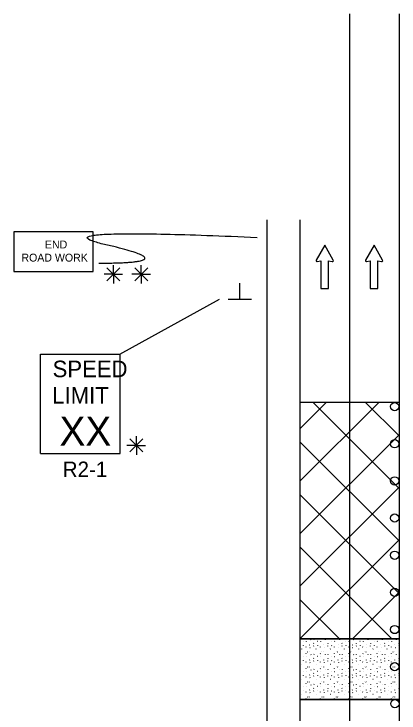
# Model space of a CAD drawing. Extents: x 16489 to 18480, y 5759 to 7026.
# Drawn here: x 16749.1 to 16935.7, y 6687.7 to 7026.4 of the extents above; entities that cross this region are included whole.
import ezdxf

# ---------------------------------------------------------------- set-up
doc = ezdxf.new("R2010")
doc.units = 0
for name, color, linetype in [('ALI_LEGAL_EX', 7, 'Continuous'), ('MT_SCRATCH_LEVEL_A', 7, 'Continuous'), ('MT_SCRATCH_LEVEL_E', 7, 'Continuous'), ('PAVT_EDGE_EX', 7, 'Continuous'), ('TRAFFIC_SIGNS_PR', 7, 'Continuous'), ('TYPICAL_TEXT_DIMEN_PR', 7, 'Continuous')]:
    doc.layers.add(name, color=color, linetype=linetype)

msp = doc.modelspace()

# ---------------------------------------------------------------- linework, layer by layer
at = {"layer": 'ALI_LEGAL_EX'}
for p, q in [((16911.66, 7026.35), (16911.66, 6197.16)), ((16935.66, 7026.35), (16935.66, 6197.16)), ((16935.66, 7026.35), (16935.66, 6197.16))]:
    msp.add_line(p, q, dxfattribs=at)
for points in [[(16911.66, 6926.35), (16911.66, 6901.35)], [(16935.66, 6926.35), (16935.66, 6901.35)], [(16911.66, 6826.35), (16911.66, 6801.35)], [(16935.66, 6826.35), (16935.66, 6801.35)], [(16911.66, 6726.35), (16911.66, 6701.35)], [(16935.66, 6726.35), (16935.66, 6701.35)]]:
    msp.add_lwpolyline(points, dxfattribs=at)
at = {"layer": 'MT_SCRATCH_LEVEL_A'}
for p, q in [((16935.66, 6838.16), (16887.66, 6838.16)), ((16935.66, 6723.62), (16887.66, 6723.62)), ((16935.66, 6694.2), (16887.66, 6694.2))]:
    msp.add_line(p, q, dxfattribs=at)
at = {"layer": 'MT_SCRATCH_LEVEL_E'}
for p, q in [((16899.66, 6914.3), (16895.55, 6907.06)), ((16903.81, 6907.06), (16899.66, 6914.3)), ((16923.57, 6914.3), (16919.46, 6907.06)), ((16927.71, 6907.06), (16923.57, 6914.3)), ((16896.03, 6906.37), (16897.81, 6906.69)), ((16897.81, 6906.69), (16897.81, 6893.43)), ((16901.55, 6893.43), (16901.55, 6906.69)), ((16901.55, 6906.69), (16903.33, 6906.37)), ((16919.94, 6906.37), (16921.72, 6906.69)), ((16921.72, 6906.69), (16921.72, 6893.43)), ((16925.46, 6893.43), (16925.46, 6906.69)), ((16925.46, 6906.69), (16927.23, 6906.37)), ((16897.81, 6893.43), (16901.55, 6893.43)), ((16921.72, 6893.43), (16925.46, 6893.43))]:
    msp.add_line(p, q, dxfattribs=at)
for centre, start, end in [((16895.96, 6906.83), 150.4248, 279.9638), ((16903.4, 6906.83), 260.0362, 29.7731), ((16919.86, 6906.83), 150.4248, 279.9638), ((16927.3, 6906.83), 260.0362, 29.7731)]:
    msp.add_arc(centre, 0.463, start, end, dxfattribs=at)
at = {"layer": 'PAVT_EDGE_EX'}
for p, q in [((16871.66, 6926.66), (16871.66, 6108.7)), ((16887.66, 6926.66), (16887.66, 6108.7)), ((16935.66, 6838.16), (16887.66, 6838.16)), ((16887.66, 6838.16), (16887.66, 6723.62)), ((16887.66, 6825.45), (16900.38, 6838.16)), ((16887.66, 6799.99), (16925.83, 6838.16)), ((16935.66, 6796.54), (16894.04, 6838.16)), ((16935.66, 6822), (16919.5, 6838.16)), ((16887.66, 6774.54), (16935.66, 6822.54)), ((16935.66, 6771.08), (16887.66, 6819.08)), ((16887.66, 6749.08), (16935.66, 6797.08)), ((16935.66, 6745.63), (16887.66, 6793.63)), ((16887.66, 6723.62), (16935.66, 6771.62)), ((16932.21, 6723.62), (16887.66, 6768.17)), ((16913.12, 6723.62), (16935.66, 6746.17)), ((16906.76, 6723.62), (16887.66, 6742.72)), ((16887.66, 6723.62), (16935.66, 6723.62)), ((16935.66, 6723.62), (16887.66, 6723.62)), ((16887.66, 6723.62), (16887.66, 6694.2)), ((16887.66, 6723.62), (16887.66, 6723.62)), ((16889.16, 6722.57), (16889.21, 6722.5)), ((16890.69, 6722.44), (16890.74, 6722.36)), ((16892.98, 6723.25), (16893.03, 6723.18)), ((16894.43, 6723.4), (16894.48, 6723.52)), ((16896.05, 6722.57), (16896.1, 6722.5)), ((16897.58, 6722.44), (16897.63, 6722.36)), ((16899.87, 6723.25), (16899.92, 6723.18)), ((16901.32, 6723.4), (16901.37, 6723.52)), ((16902.94, 6722.57), (16902.99, 6722.5)), ((16904.47, 6722.44), (16904.52, 6722.36)), ((16906.76, 6723.25), (16906.81, 6723.18)), ((16908.21, 6723.4), (16908.26, 6723.52)), ((16909.82, 6722.57), (16909.88, 6722.5)), ((16911.35, 6722.44), (16911.4, 6722.36)), ((16913.64, 6723.25), (16913.69, 6723.18)), ((16915.09, 6723.4), (16915.14, 6723.52)), ((16916.71, 6722.57), (16916.76, 6722.5)), ((16918.24, 6722.44), (16918.29, 6722.36)), ((16920.53, 6723.25), (16920.58, 6723.18)), ((16921.98, 6723.4), (16922.03, 6723.52)), ((16923.6, 6722.57), (16923.65, 6722.5)), ((16925.13, 6722.44), (16925.18, 6722.36)), ((16927.42, 6723.25), (16927.47, 6723.18)), ((16928.87, 6723.4), (16928.92, 6723.52)), ((16930.49, 6722.57), (16930.54, 6722.5)), ((16932.02, 6722.44), (16932.07, 6722.36)), ((16934.31, 6723.25), (16934.36, 6723.18)), ((16889.21, 6720.37), (16889.26, 6720.29)), ((16890.49, 6719.79), (16890.5, 6719.67)), ((16892.33, 6720.65), (16892.38, 6720.76)), ((16892.52, 6719.45), (16892.57, 6719.37)), ((16894.26, 6721.52), (16894.31, 6721.44)), ((16894.3, 6720.11), (16894.35, 6720.23)), ((16896.1, 6720.37), (16896.15, 6720.29)), ((16897.38, 6719.79), (16897.39, 6719.67)), ((16899.22, 6720.65), (16899.27, 6720.76)), ((16899.41, 6719.45), (16899.46, 6719.37)), ((16901.15, 6721.52), (16901.2, 6721.44)), ((16901.19, 6720.11), (16901.24, 6720.23)), ((16902.99, 6720.37), (16903.04, 6720.29)), ((16904.27, 6719.79), (16904.28, 6719.67)), ((16906.11, 6720.65), (16906.16, 6720.76)), ((16906.3, 6719.45), (16906.35, 6719.37)), ((16908.03, 6721.52), (16908.08, 6721.44)), ((16908.08, 6720.11), (16908.13, 6720.23)), ((16909.87, 6720.37), (16909.92, 6720.29)), ((16911.15, 6719.79), (16911.17, 6719.67)), ((16912.99, 6720.65), (16913.05, 6720.76)), ((16913.18, 6719.45), (16913.24, 6719.37)), ((16914.92, 6721.52), (16914.97, 6721.44)), ((16914.96, 6720.11), (16915.01, 6720.23)), ((16916.76, 6720.37), (16916.81, 6720.29)), ((16918.04, 6719.79), (16918.05, 6719.67)), ((16919.88, 6720.65), (16919.93, 6720.76)), ((16920.07, 6719.45), (16920.12, 6719.37)), ((16921.81, 6721.52), (16921.86, 6721.44)), ((16921.85, 6720.11), (16921.9, 6720.23)), ((16923.65, 6720.37), (16923.7, 6720.29)), ((16924.93, 6719.79), (16924.94, 6719.67)), ((16926.77, 6720.65), (16926.82, 6720.76)), ((16926.96, 6719.45), (16927.01, 6719.37)), ((16928.7, 6721.52), (16928.75, 6721.44)), ((16928.74, 6720.11), (16928.79, 6720.23)), ((16930.53, 6720.37), (16930.59, 6720.29)), ((16931.82, 6719.79), (16931.83, 6719.67)), ((16933.66, 6720.65), (16933.71, 6720.76)), ((16933.85, 6719.45), (16933.9, 6719.37)), ((16935.58, 6721.52), (16935.64, 6721.44)), ((16935.63, 6720.11), (16935.66, 6720.2)), ((16888.59, 6718.61), (16888.64, 6718.73)), ((16890.61, 6716.42), (16890.66, 6716.53)), ((16891.38, 6717.38), (16891.43, 6717.3)), ((16892.11, 6717.35), (16892.16, 6717.27)), ((16892.98, 6715.97), (16893.03, 6715.89)), ((16894.43, 6716.12), (16894.48, 6716.24)), ((16895.48, 6718.61), (16895.53, 6718.73)), ((16897.5, 6716.42), (16897.55, 6716.53)), ((16898.26, 6717.38), (16898.31, 6717.3)), ((16899, 6717.35), (16899.05, 6717.27)), ((16899.87, 6715.97), (16899.92, 6715.89)), ((16901.32, 6716.12), (16901.37, 6716.24)), ((16902.37, 6718.61), (16902.42, 6718.73)), ((16904.39, 6716.42), (16904.44, 6716.53)), ((16905.15, 6717.38), (16905.2, 6717.3)), ((16905.89, 6717.35), (16905.94, 6717.27)), ((16906.76, 6715.97), (16906.81, 6715.89)), ((16908.21, 6716.12), (16908.26, 6716.24)), ((16909.25, 6718.61), (16909.31, 6718.73)), ((16911.27, 6716.42), (16911.33, 6716.53)), ((16912.04, 6717.38), (16912.09, 6717.3)), ((16912.78, 6717.35), (16912.83, 6717.27)), ((16913.64, 6715.97), (16913.69, 6715.89)), ((16915.09, 6716.12), (16915.14, 6716.24)), ((16916.14, 6718.61), (16916.19, 6718.73)), ((16918.16, 6716.42), (16918.21, 6716.53)), ((16918.92, 6717.38), (16918.98, 6717.3)), ((16919.66, 6717.35), (16919.71, 6717.27)), ((16920.53, 6715.97), (16920.58, 6715.89)), ((16921.98, 6716.12), (16922.03, 6716.24)), ((16923.03, 6718.61), (16923.08, 6718.73)), ((16925.05, 6716.42), (16925.1, 6716.53)), ((16925.81, 6717.38), (16925.86, 6717.3)), ((16926.55, 6717.35), (16926.6, 6717.27)), ((16927.42, 6715.97), (16927.47, 6715.89)), ((16928.87, 6716.12), (16928.92, 6716.24)), ((16929.92, 6718.61), (16929.97, 6718.73)), ((16931.94, 6716.42), (16931.99, 6716.53)), ((16932.7, 6717.38), (16932.75, 6717.3)), ((16933.44, 6717.35), (16933.49, 6717.27)), ((16934.31, 6715.97), (16934.36, 6715.89)), ((16889.16, 6715.29), (16889.21, 6715.21)), ((16889.21, 6713.08), (16889.26, 6713)), ((16890.49, 6712.51), (16890.5, 6712.39)), ((16890.69, 6715.15), (16890.74, 6715.07)), ((16892.33, 6713.36), (16892.38, 6713.48)), ((16892.52, 6712.16), (16892.57, 6712.08)), ((16894.26, 6714.23), (16894.31, 6714.15)), ((16894.3, 6712.83), (16894.35, 6712.95)), ((16896.05, 6715.29), (16896.1, 6715.21)), ((16896.1, 6713.08), (16896.15, 6713)), ((16897.38, 6712.51), (16897.39, 6712.39)), ((16897.58, 6715.15), (16897.63, 6715.07)), ((16899.22, 6713.36), (16899.27, 6713.48)), ((16899.41, 6712.16), (16899.46, 6712.08)), ((16901.15, 6714.23), (16901.2, 6714.15)), ((16901.19, 6712.83), (16901.24, 6712.95)), ((16902.94, 6715.29), (16902.99, 6715.21)), ((16902.99, 6713.08), (16903.04, 6713)), ((16904.27, 6712.51), (16904.28, 6712.39)), ((16904.47, 6715.15), (16904.52, 6715.07)), ((16906.11, 6713.36), (16906.16, 6713.48)), ((16906.3, 6712.16), (16906.35, 6712.08)), ((16908.03, 6714.23), (16908.08, 6714.15)), ((16908.08, 6712.83), (16908.13, 6712.95)), ((16909.82, 6715.29), (16909.88, 6715.21)), ((16909.87, 6713.08), (16909.92, 6713)), ((16911.15, 6712.51), (16911.17, 6712.39)), ((16911.35, 6715.15), (16911.4, 6715.07)), ((16912.99, 6713.36), (16913.05, 6713.48)), ((16913.18, 6712.16), (16913.24, 6712.08)), ((16914.92, 6714.23), (16914.97, 6714.15)), ((16914.96, 6712.83), (16915.01, 6712.95)), ((16916.71, 6715.29), (16916.76, 6715.21)), ((16916.76, 6713.08), (16916.81, 6713)), ((16918.04, 6712.51), (16918.05, 6712.39)), ((16918.24, 6715.15), (16918.29, 6715.07)), ((16919.88, 6713.36), (16919.93, 6713.48)), ((16920.07, 6712.16), (16920.12, 6712.08)), ((16921.81, 6714.23), (16921.86, 6714.15)), ((16921.85, 6712.83), (16921.9, 6712.95)), ((16923.6, 6715.29), (16923.65, 6715.21)), ((16923.65, 6713.08), (16923.7, 6713)), ((16924.93, 6712.51), (16924.94, 6712.39)), ((16925.13, 6715.15), (16925.18, 6715.07)), ((16926.77, 6713.36), (16926.82, 6713.48)), ((16926.96, 6712.16), (16927.01, 6712.08)), ((16928.7, 6714.23), (16928.75, 6714.15)), ((16928.74, 6712.83), (16928.79, 6712.95)), ((16930.49, 6715.29), (16930.54, 6715.21)), ((16930.53, 6713.08), (16930.59, 6713)), ((16931.82, 6712.51), (16931.83, 6712.39)), ((16932.02, 6715.15), (16932.07, 6715.07)), ((16933.66, 6713.36), (16933.71, 6713.48)), ((16933.85, 6712.16), (16933.9, 6712.08)), ((16935.58, 6714.23), (16935.64, 6714.15)), ((16935.63, 6712.83), (16935.66, 6712.92)), ((16888.59, 6711.33), (16888.64, 6711.44)), ((16890.61, 6709.13), (16890.66, 6709.25)), ((16891.38, 6710.09), (16891.43, 6710.01)), ((16892.11, 6710.06), (16892.16, 6709.98)), ((16894.43, 6708.83), (16894.48, 6708.95)), ((16895.48, 6711.33), (16895.53, 6711.44)), ((16897.5, 6709.13), (16897.55, 6709.25)), ((16898.26, 6710.09), (16898.31, 6710.01)), ((16899, 6710.06), (16899.05, 6709.98)), ((16901.32, 6708.83), (16901.37, 6708.95)), ((16902.37, 6711.33), (16902.42, 6711.44)), ((16904.39, 6709.13), (16904.44, 6709.25)), ((16905.15, 6710.09), (16905.2, 6710.01)), ((16905.89, 6710.06), (16905.94, 6709.98)), ((16908.21, 6708.83), (16908.26, 6708.95)), ((16909.25, 6711.33), (16909.31, 6711.44)), ((16911.27, 6709.13), (16911.33, 6709.25)), ((16912.04, 6710.09), (16912.09, 6710.01)), ((16912.78, 6710.06), (16912.83, 6709.98)), ((16915.09, 6708.83), (16915.14, 6708.95)), ((16916.14, 6711.33), (16916.19, 6711.44)), ((16918.16, 6709.13), (16918.21, 6709.25)), ((16918.92, 6710.09), (16918.98, 6710.01)), ((16919.66, 6710.06), (16919.71, 6709.98)), ((16921.98, 6708.83), (16922.03, 6708.95)), ((16923.03, 6711.33), (16923.08, 6711.44)), ((16925.05, 6709.13), (16925.1, 6709.25)), ((16925.81, 6710.09), (16925.86, 6710.01)), ((16926.55, 6710.06), (16926.6, 6709.98)), ((16928.87, 6708.83), (16928.92, 6708.95)), ((16929.92, 6711.33), (16929.97, 6711.44)), ((16931.94, 6709.13), (16931.99, 6709.25)), ((16932.7, 6710.09), (16932.75, 6710.01)), ((16933.44, 6710.06), (16933.49, 6709.98)), ((16889.16, 6708.01), (16889.21, 6707.93)), ((16889.21, 6705.8), (16889.26, 6705.72)), ((16890.69, 6707.86), (16890.74, 6707.79)), ((16892.33, 6706.08), (16892.38, 6706.19)), ((16892.98, 6708.68), (16893.03, 6708.61)), ((16894.26, 6706.95), (16894.31, 6706.87)), ((16894.3, 6705.55), (16894.35, 6705.66)), ((16896.05, 6708.01), (16896.1, 6707.93)), ((16896.1, 6705.8), (16896.15, 6705.72)), ((16897.58, 6707.86), (16897.63, 6707.79)), ((16899.22, 6706.08), (16899.27, 6706.19)), ((16899.87, 6708.68), (16899.92, 6708.61)), ((16901.15, 6706.95), (16901.2, 6706.87)), ((16901.19, 6705.55), (16901.24, 6705.66)), ((16902.94, 6708.01), (16902.99, 6707.93)), ((16902.99, 6705.8), (16903.04, 6705.72)), ((16904.47, 6707.86), (16904.52, 6707.79)), ((16906.11, 6706.08), (16906.16, 6706.19)), ((16906.76, 6708.68), (16906.81, 6708.61)), ((16908.03, 6706.95), (16908.08, 6706.87)), ((16908.08, 6705.55), (16908.13, 6705.66)), ((16909.82, 6708.01), (16909.88, 6707.93)), ((16909.87, 6705.8), (16909.92, 6705.72)), ((16911.35, 6707.86), (16911.4, 6707.79)), ((16912.99, 6706.08), (16913.05, 6706.19)), ((16913.64, 6708.68), (16913.69, 6708.61)), ((16914.92, 6706.95), (16914.97, 6706.87)), ((16914.96, 6705.55), (16915.01, 6705.66)), ((16916.71, 6708.01), (16916.76, 6707.93)), ((16916.76, 6705.8), (16916.81, 6705.72)), ((16918.24, 6707.86), (16918.29, 6707.79)), ((16919.88, 6706.08), (16919.93, 6706.19)), ((16920.53, 6708.68), (16920.58, 6708.61)), ((16921.81, 6706.95), (16921.86, 6706.87)), ((16921.85, 6705.55), (16921.9, 6705.66)), ((16923.6, 6708.01), (16923.65, 6707.93)), ((16923.65, 6705.8), (16923.7, 6705.72)), ((16925.13, 6707.86), (16925.18, 6707.79)), ((16926.77, 6706.08), (16926.82, 6706.19)), ((16927.42, 6708.68), (16927.47, 6708.61)), ((16928.7, 6706.95), (16928.75, 6706.87)), ((16928.74, 6705.55), (16928.79, 6705.66)), ((16930.49, 6708.01), (16930.54, 6707.93)), ((16930.53, 6705.8), (16930.59, 6705.72)), ((16932.02, 6707.86), (16932.07, 6707.79)), ((16933.66, 6706.08), (16933.71, 6706.19)), ((16934.31, 6708.68), (16934.36, 6708.61)), ((16935.58, 6706.95), (16935.64, 6706.87)), ((16935.63, 6705.55), (16935.66, 6705.63)), ((16888.59, 6704.04), (16888.64, 6704.16)), ((16890.49, 6705.22), (16890.5, 6705.1)), ((16891.38, 6702.81), (16891.43, 6702.73)), ((16892.11, 6702.78), (16892.16, 6702.7)), ((16892.52, 6704.88), (16892.57, 6704.8)), ((16895.48, 6704.04), (16895.53, 6704.16)), ((16897.38, 6705.22), (16897.39, 6705.1)), ((16898.26, 6702.81), (16898.31, 6702.73)), ((16899, 6702.78), (16899.05, 6702.7)), ((16899.41, 6704.88), (16899.46, 6704.8)), ((16902.37, 6704.04), (16902.42, 6704.16)), ((16904.27, 6705.22), (16904.28, 6705.1)), ((16905.15, 6702.81), (16905.2, 6702.73)), ((16905.89, 6702.78), (16905.94, 6702.7)), ((16906.3, 6704.88), (16906.35, 6704.8)), ((16909.25, 6704.04), (16909.31, 6704.16)), ((16911.15, 6705.22), (16911.17, 6705.1)), ((16912.04, 6702.81), (16912.09, 6702.73)), ((16912.78, 6702.78), (16912.83, 6702.7)), ((16913.18, 6704.88), (16913.24, 6704.8)), ((16916.14, 6704.04), (16916.19, 6704.16)), ((16918.04, 6705.22), (16918.05, 6705.1)), ((16918.92, 6702.81), (16918.98, 6702.73)), ((16919.66, 6702.78), (16919.71, 6702.7)), ((16920.07, 6704.88), (16920.12, 6704.8)), ((16923.03, 6704.04), (16923.08, 6704.16)), ((16924.93, 6705.22), (16924.94, 6705.1)), ((16925.81, 6702.81), (16925.86, 6702.73)), ((16926.55, 6702.78), (16926.6, 6702.7)), ((16926.96, 6704.88), (16927.01, 6704.8)), ((16929.92, 6704.04), (16929.97, 6704.16)), ((16931.82, 6705.22), (16931.83, 6705.1)), ((16932.7, 6702.81), (16932.75, 6702.73)), ((16933.44, 6702.78), (16933.49, 6702.7)), ((16933.85, 6704.88), (16933.9, 6704.8)), ((16889.16, 6700.72), (16889.21, 6700.64)), ((16890.61, 6701.85), (16890.66, 6701.96)), ((16890.69, 6700.58), (16890.74, 6700.5)), ((16892.33, 6698.79), (16892.38, 6698.91)), ((16892.98, 6701.4), (16893.03, 6701.32)), ((16894.26, 6699.66), (16894.31, 6699.58)), ((16894.43, 6701.55), (16894.48, 6701.67)), ((16896.05, 6700.72), (16896.1, 6700.64)), ((16897.5, 6701.85), (16897.55, 6701.96)), ((16897.58, 6700.58), (16897.63, 6700.5)), ((16899.22, 6698.79), (16899.27, 6698.91)), ((16899.87, 6701.4), (16899.92, 6701.32)), ((16901.15, 6699.66), (16901.2, 6699.58)), ((16901.32, 6701.55), (16901.37, 6701.67)), ((16902.94, 6700.72), (16902.99, 6700.64)), ((16904.39, 6701.85), (16904.44, 6701.96)), ((16904.47, 6700.58), (16904.52, 6700.5)), ((16906.11, 6698.79), (16906.16, 6698.91)), ((16906.76, 6701.4), (16906.81, 6701.32)), ((16908.03, 6699.66), (16908.08, 6699.58)), ((16908.21, 6701.55), (16908.26, 6701.67)), ((16909.82, 6700.72), (16909.88, 6700.64)), ((16911.27, 6701.85), (16911.33, 6701.96)), ((16911.35, 6700.58), (16911.4, 6700.5)), ((16912.99, 6698.79), (16913.05, 6698.91)), ((16913.64, 6701.4), (16913.69, 6701.32)), ((16914.92, 6699.66), (16914.97, 6699.58)), ((16915.09, 6701.55), (16915.14, 6701.67)), ((16916.71, 6700.72), (16916.76, 6700.64)), ((16918.16, 6701.85), (16918.21, 6701.96)), ((16918.24, 6700.58), (16918.29, 6700.5)), ((16919.88, 6698.79), (16919.93, 6698.91)), ((16920.53, 6701.4), (16920.58, 6701.32)), ((16921.81, 6699.66), (16921.86, 6699.58)), ((16921.98, 6701.55), (16922.03, 6701.67)), ((16923.6, 6700.72), (16923.65, 6700.64)), ((16925.05, 6701.85), (16925.1, 6701.96)), ((16925.13, 6700.58), (16925.18, 6700.5)), ((16926.77, 6698.79), (16926.82, 6698.91)), ((16927.42, 6701.4), (16927.47, 6701.32)), ((16928.7, 6699.66), (16928.75, 6699.58)), ((16928.87, 6701.55), (16928.92, 6701.67)), ((16930.49, 6700.72), (16930.54, 6700.64)), ((16931.94, 6701.85), (16931.99, 6701.96)), ((16932.02, 6700.58), (16932.07, 6700.5)), ((16933.66, 6698.79), (16933.71, 6698.91)), ((16934.31, 6701.4), (16934.36, 6701.32)), ((16935.58, 6699.66), (16935.64, 6699.58)), ((16888.59, 6696.76), (16888.64, 6696.88)), ((16889.21, 6698.51), (16889.26, 6698.43)), ((16890.49, 6697.94), (16890.5, 6697.82)), ((16891.38, 6695.52), (16891.43, 6695.44)), ((16892.11, 6695.49), (16892.16, 6695.41)), ((16892.52, 6697.59), (16892.57, 6697.51)), ((16894.3, 6698.26), (16894.35, 6698.38)), ((16895.48, 6696.76), (16895.53, 6696.88)), ((16896.1, 6698.51), (16896.15, 6698.43)), ((16897.38, 6697.94), (16897.39, 6697.82)), ((16898.26, 6695.52), (16898.31, 6695.44)), ((16899, 6695.49), (16899.05, 6695.41)), ((16899.41, 6697.59), (16899.46, 6697.51)), ((16901.19, 6698.26), (16901.24, 6698.38)), ((16902.37, 6696.76), (16902.42, 6696.88)), ((16902.99, 6698.51), (16903.04, 6698.43)), ((16904.27, 6697.94), (16904.28, 6697.82)), ((16905.15, 6695.52), (16905.2, 6695.44)), ((16905.89, 6695.49), (16905.94, 6695.41)), ((16906.3, 6697.59), (16906.35, 6697.51)), ((16908.08, 6698.26), (16908.13, 6698.38)), ((16909.25, 6696.76), (16909.31, 6696.88)), ((16909.87, 6698.51), (16909.92, 6698.43)), ((16911.15, 6697.94), (16911.17, 6697.82)), ((16912.04, 6695.52), (16912.09, 6695.44)), ((16912.78, 6695.49), (16912.83, 6695.41)), ((16913.18, 6697.59), (16913.24, 6697.51)), ((16914.96, 6698.26), (16915.01, 6698.38)), ((16916.14, 6696.76), (16916.19, 6696.88)), ((16916.76, 6698.51), (16916.81, 6698.43)), ((16918.04, 6697.94), (16918.05, 6697.82)), ((16918.92, 6695.52), (16918.98, 6695.44)), ((16919.66, 6695.49), (16919.71, 6695.41)), ((16920.07, 6697.59), (16920.12, 6697.51)), ((16921.85, 6698.26), (16921.9, 6698.38)), ((16923.03, 6696.76), (16923.08, 6696.88)), ((16923.65, 6698.51), (16923.7, 6698.43)), ((16924.93, 6697.94), (16924.94, 6697.82)), ((16925.81, 6695.52), (16925.86, 6695.44)), ((16926.55, 6695.49), (16926.6, 6695.41)), ((16926.96, 6697.59), (16927.01, 6697.51)), ((16928.74, 6698.26), (16928.79, 6698.38)), ((16929.92, 6696.76), (16929.97, 6696.88)), ((16930.53, 6698.51), (16930.59, 6698.43)), ((16931.82, 6697.94), (16931.83, 6697.82)), ((16932.7, 6695.52), (16932.75, 6695.44)), ((16933.44, 6695.49), (16933.49, 6695.41)), ((16933.85, 6697.59), (16933.9, 6697.51)), ((16935.63, 6698.26), (16935.66, 6698.35)), ((16887.66, 6694.2), (16935.66, 6694.2)), ((16890.61, 6694.56), (16890.66, 6694.68)), ((16894.43, 6694.26), (16894.48, 6694.38)), ((16897.5, 6694.56), (16897.55, 6694.68)), ((16901.32, 6694.26), (16901.37, 6694.38)), ((16904.39, 6694.56), (16904.44, 6694.68)), ((16908.21, 6694.26), (16908.26, 6694.38)), ((16911.27, 6694.56), (16911.33, 6694.68)), ((16915.09, 6694.26), (16915.14, 6694.38)), ((16918.16, 6694.56), (16918.21, 6694.68)), ((16921.98, 6694.26), (16922.03, 6694.38)), ((16925.05, 6694.56), (16925.1, 6694.68)), ((16928.87, 6694.26), (16928.92, 6694.38)), ((16931.94, 6694.56), (16931.99, 6694.68))]:
    msp.add_line(p, q, dxfattribs=at)
at = {"layer": 'TRAFFIC_SIGNS_PR'}
for p, q in [((16762.02, 6861.55), (16800.47, 6861.55)), ((16762.02, 6813.49), (16762.02, 6861.55)), ((16800.47, 6813.49), (16800.47, 6861.55)), ((16762.02, 6813.49), (16800.47, 6813.49))]:
    msp.add_line(p, q, dxfattribs=at)
msp.add_lwpolyline([(16749.09, 6901.65), (16787.49, 6901.65), (16787.49, 6920.85), (16749.09, 6920.85)], close=True, dxfattribs=at)
for centre in [(16933.56, 6836.14), (16933.56, 6818.14), (16933.56, 6800.14), (16933.56, 6782.14), (16933.56, 6764.14), (16933.56, 6746.14), (16933.56, 6728.14), (16933.56, 6710.14), (16933.66, 6692.2)]:
    msp.add_circle(centre, 2, dxfattribs=at)
msp.add_open_spline([(16790.14, 6905.64), (16832.65, 6905.64), (16756.13, 6923.05), (16866.92, 6918.11)], degree=2, dxfattribs=at)
at = {"layer": 'TYPICAL_TEXT_DIMEN_PR'}
for p, q in [((16794.08, 6903.41), (16800.45, 6897.03)), ((16800.45, 6903.41), (16794.08, 6897.03)), ((16797.26, 6900.22), (16797.26, 6904.68)), ((16807.58, 6903.41), (16813.96, 6897.03)), ((16813.96, 6903.41), (16807.58, 6897.03)), ((16810.77, 6900.22), (16810.77, 6904.68)), ((16797.26, 6900.22), (16792.73, 6900.22)), ((16797.26, 6900.22), (16800.45, 6900.22)), ((16797.26, 6900.22), (16801.74, 6900.22)), ((16797.26, 6900.22), (16797.26, 6895.72)), ((16810.77, 6900.22), (16806.24, 6900.22)), ((16810.77, 6900.22), (16813.96, 6900.22)), ((16810.77, 6900.22), (16815.25, 6900.22)), ((16810.77, 6900.22), (16810.77, 6895.72)), ((16858.54, 6888.16), (16858.54, 6895.95)), ((16800.42, 6861.55), (16848.66, 6888.16)), ((16852.91, 6888.16), (16864.16, 6888.16)), ((16805.19, 6820.53), (16811.56, 6814.15)), ((16811.56, 6820.53), (16805.19, 6814.15)), ((16808.38, 6817.34), (16808.38, 6821.8)), ((16808.38, 6817.34), (16803.84, 6817.34)), ((16808.38, 6817.34), (16811.56, 6817.34)), ((16808.38, 6817.34), (16812.85, 6817.34)), ((16808.38, 6817.34), (16808.38, 6812.84))]:
    msp.add_line(p, q, dxfattribs=at)

# ---------------------------------------------------------------- texts
at = {"layer": 'TRAFFIC_SIGNS_PR'}
for s, height, p in [('END', 3.831, (16764.09, 6912.77)), ('ROAD WORK', 3.831, (16752.7, 6906.39)), ('SPEED', 8.01, (16767.8, 6850.4)), ('LIMIT', 8.01, (16767.64, 6837.58)), ('XX', 14.048, (16771.15, 6817.25)), ('R2-1', 7.449, (16772.71, 6802.04))]:
    msp.add_text(s, height=height, dxfattribs=at).set_placement(p)

doc.saveas('drawing.dxf')
